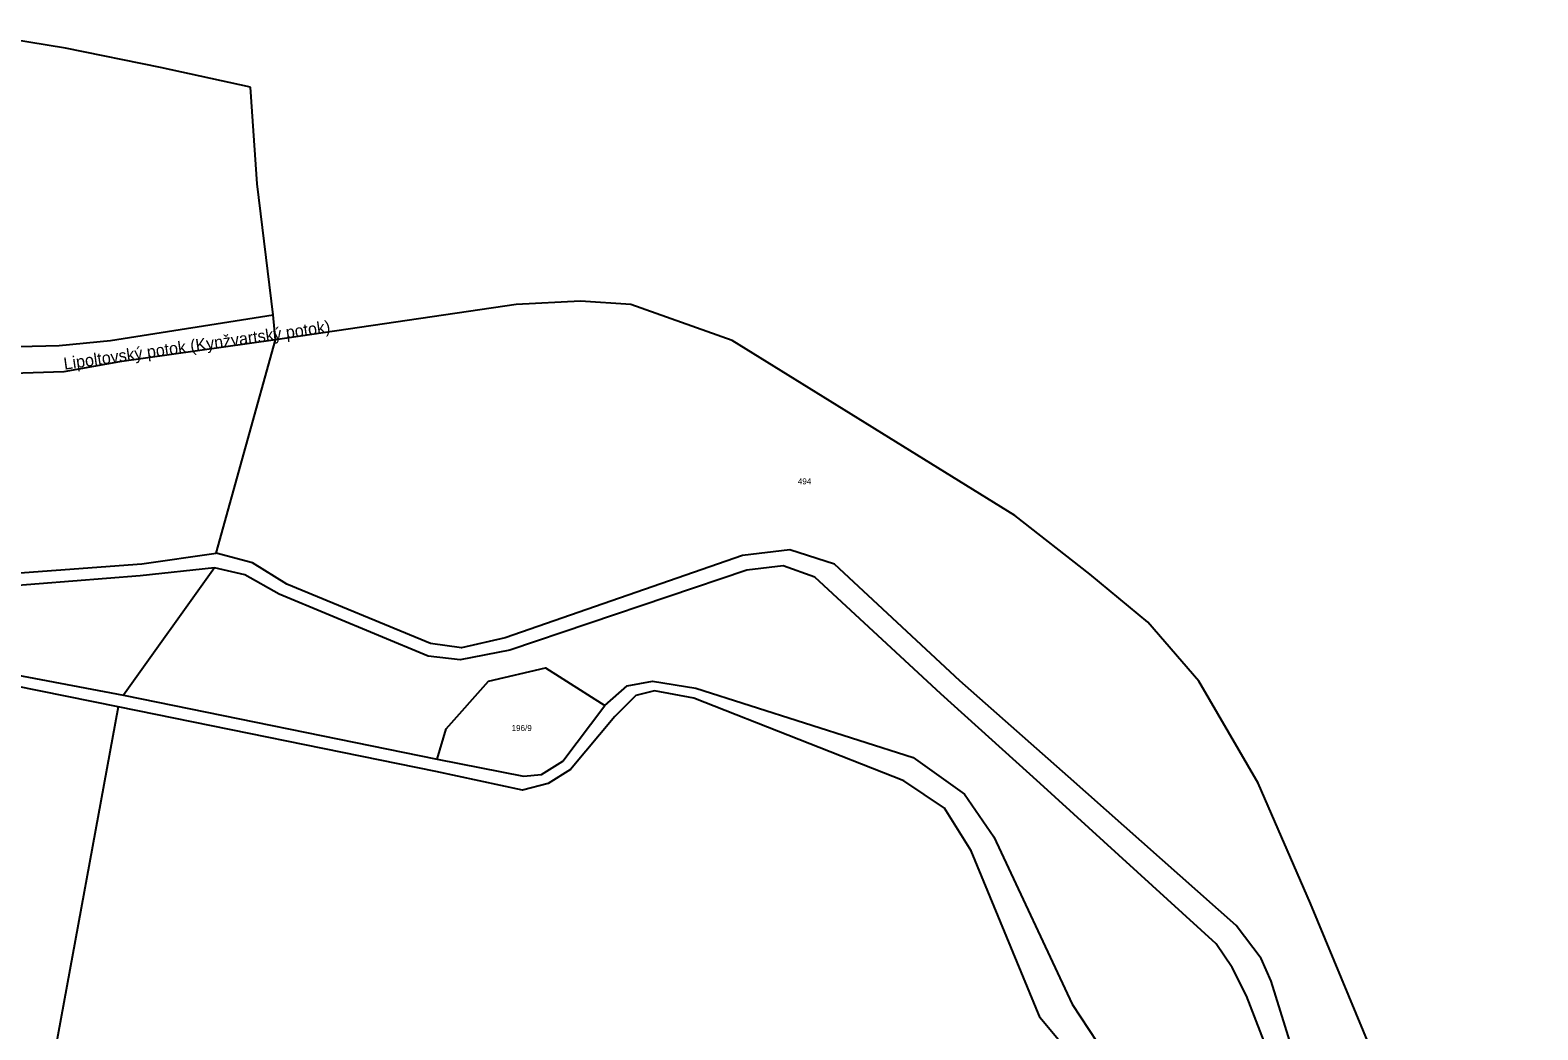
# Model space of a CAD drawing. Extents: x -880531 to -877616, y -1023932 to -1021350.
# Drawn here: x -878177.4 to -877751.2, y -1022635.5 to -1022353.1 of the extents above; entities that cross this region are included whole.
import ezdxf

# ---------------------------------------------------------------- set-up
doc = ezdxf.new("R2010")
doc.units = 0
for name, color, linetype in [('Hranice parcel', 7, 'Continuous'), ('Parcelní čísla', 7, 'Continuous'), ('Pop  PČ popisy', 7, 'Continuous')]:
    doc.layers.add(name, color=color, linetype=linetype)

msp = doc.modelspace()

# ---------------------------------------------------------------- linework, layer by layer
at = {"layer": 'Hranice parcel'}
for p, q in [((-878114.65, -1022376), (-878115.1, -1022369.21)), ((-878113.29, -1022396.52), (-878114.65, -1022376)), ((-878108.69, -1022433.47), (-878113.29, -1022396.52)), ((-878021.82, -1022429.61), (-878040.06, -1022430.56)), ((-878108.11, -1022440.58), (-878108.69, -1022433.47)), ((-878040.06, -1022430.56), (-878108.11, -1022440.58)), ((-878124.82, -1022500.78), (-878108.11, -1022440.58)), ((-878125.35, -1022504.99), (-878151.01, -1022540.9)), ((-878151.01, -1022540.9), (-878062.4, -1022559.06)), ((-878152.5, -1022544.22), (-878174.22, -1022662.33))]:
    msp.add_line(p, q, dxfattribs=at)
for points in [[(-878115.1, -1022369.21), (-878140.56, -1022363.64), (-878167.43, -1022358.13), (-878198.58, -1022353.06)], [(-877774.21, -1022699.12), (-877815.48, -1022599.78), (-877830.28, -1022565.82), (-877847.02, -1022536.96), (-877861.42, -1022520.32), (-877877.81, -1022506.75), (-877899.07, -1022490.23), (-877979.01, -1022440.72), (-878007.65, -1022430.59), (-878021.82, -1022429.61)], [(-878452.29, -1022470.77), (-878434.2, -1022474.39), (-878410.19, -1022472.17), (-878361.38, -1022456.95), (-878336.49, -1022449.29), (-878323.26, -1022446.51), (-878300.76, -1022445.25), (-878207.33, -1022443.11), (-878169.2, -1022442.13), (-878154.71, -1022440.73), (-878108.69, -1022433.47)], [(-878108.11, -1022440.58), (-878152.15, -1022446.77), (-878167.86, -1022449.63), (-878217.16, -1022451.24), (-878301.33, -1022453.9), (-878333.67, -1022456.67), (-878366.21, -1022467.52), (-878407.13, -1022480.7), (-878435.64, -1022482.95), (-878455.12, -1022478.73), (-878537.04, -1022450.63), (-878561.34, -1022444.97), (-878578.99, -1022444.28), (-878605.69, -1022449.33), (-878637.81, -1022454.4), (-878653.86, -1022459.64), (-878669.06, -1022467.56), (-878706.56, -1022499.73), (-878724.15, -1022512.39), (-878736.44, -1022518.55), (-878757.9, -1022522.41)], [(-878757.9, -1022522.41), (-878743.38, -1022532.72), (-878730.23, -1022539.4), (-878709.85, -1022535.98), (-878694.32, -1022525.35), (-878670.27, -1022495.13), (-878649.48, -1022475.44), (-878635.27, -1022470.68), (-878614.41, -1022478.04), (-878543.73, -1022482.35), (-878506.92, -1022500.7), (-878475.11, -1022508.02), (-878399.08, -1022508.59), (-878373.94, -1022502.74), (-878346.19, -1022490.2), (-878334.94, -1022490.41), (-878279.22, -1022499.74), (-878220.51, -1022507.42), (-878194.43, -1022507.39), (-878145.84, -1022503.8), (-878124.82, -1022500.78)], [(-878125.35, -1022504.99), (-878146.35, -1022507.21), (-878194.02, -1022510.96), (-878220.76, -1022511.05), (-878280.27, -1022503.97), (-878335.4, -1022493.58), (-878344.86, -1022493.55), (-878371.73, -1022505.4), (-878399.1, -1022512.43), (-878475.7, -1022511.16), (-878508.77, -1022503.35), (-878545.47, -1022484.68), (-878615.6, -1022481.24), (-878635.5, -1022474.3), (-878648.14, -1022478.45), (-878668.08, -1022496.96), (-878691.68, -1022527.88), (-878708.19, -1022539.68), (-878731.2, -1022543.61), (-878748.07, -1022535.1), (-878763.51, -1022523.14)], [(-877774.21, -1022699.12), (-877785.15, -1022681.23), (-877817.84, -1022649.87), (-877826.63, -1022621.76), (-877829.39, -1022615.33), (-877836.46, -1022606.02), (-877883.97, -1022563.9), (-877914.65, -1022536.94), (-877950.08, -1022503.93), (-877962.7, -1022499.85), (-877976.09, -1022501.47), (-878043.14, -1022524.77), (-878055.52, -1022527.59), (-878064.21, -1022526.36), (-878104.86, -1022509.57), (-878114.56, -1022503.51), (-878124.82, -1022500.78)], [(-877810.95, -1022891.71), (-877757.7, -1022868.07), (-877755.3, -1022863.36), (-877756.99, -1022844.34), (-877751.2, -1022776.89), (-877754.01, -1022763.91), (-877778.95, -1022701.2), (-877790.12, -1022684.76), (-877822.46, -1022654.59), (-877833.6, -1022625.94), (-877837.59, -1022617.9), (-877842.13, -1022611.17), (-877891.85, -1022565.86), (-877919.95, -1022540.56), (-877955.55, -1022507.61), (-877964.52, -1022504.4), (-877974.82, -1022505.6), (-878041.79, -1022528.2), (-878055.84, -1022531), (-878064.89, -1022529.96), (-878107.07, -1022512.45), (-878116.76, -1022506.91), (-878125.35, -1022504.99)], [(-878772.34, -1022525.45), (-878758.55, -1022537.32), (-878734.74, -1022552.47), (-878725.11, -1022552.52), (-878697.59, -1022542.6), (-878692.56, -1022542.42), (-878672.91, -1022533.58), (-878660.33, -1022531.18), (-878648.04, -1022531.76), (-878616.24, -1022536.33), (-878607.61, -1022539.29), (-878559.76, -1022547.29), (-878533.18, -1022551.67), (-878521.77, -1022552.65), (-878440.9, -1022540.29), (-878419.64, -1022538.34), (-878389.99, -1022539.7), (-878317.85, -1022548.39), (-878303.92, -1022544.55), (-878256.37, -1022525.75), (-878245.48, -1022524.13), (-878233.68, -1022525.33), (-878151.01, -1022540.9)], [(-878152.5, -1022544.22), (-878234.05, -1022527.78), (-878244.93, -1022527.2), (-878256.18, -1022528.49), (-878262.91, -1022531.2)], [(-878062.4, -1022559.06), (-878059.82, -1022550.43), (-878047.81, -1022536.98), (-878031.74, -1022533.19), (-878015.01, -1022543.9)], [(-878015.01, -1022543.9), (-878008.64, -1022538.33), (-878001.45, -1022536.99), (-877989.21, -1022538.94), (-877927.83, -1022558.6), (-877913.24, -1022568.89), (-877905, -1022581.01), (-877882.83, -1022628.25), (-877875.74, -1022639)], [(-877881.25, -1022644.92), (-877891.87, -1022632.09), (-877911.37, -1022584.94), (-877918.91, -1022572.84), (-877930.4, -1022565.15), (-877989.82, -1022541.75), (-878000.9, -1022539.74), (-878006.19, -1022541.03), (-878012.13, -1022546.99), (-878024.63, -1022561.95), (-878030.95, -1022565.94), (-878038.25, -1022567.79), (-878062.75, -1022562.53), (-878152.5, -1022544.22)], [(-878062.4, -1022559.06), (-878037.99, -1022563.86), (-878032.84, -1022563.38), (-878026.83, -1022559.57), (-878015.01, -1022543.9)]]:
    msp.add_lwpolyline(points, dxfattribs=at)

# ---------------------------------------------------------------- texts
at = {"layer": 'Parcelní čísla'}
for s, p in [('494', (-877960.39, -1022481.38)), ('196/9', (-878041.32, -1022551.08))]:
    msp.add_text(s, height=1.7, dxfattribs=at).set_placement(p)
at = {"layer": 'Pop  PČ popisy'}
msp.add_text('Lipoltovský potok (Kynžvartský potok)', height=3.4, rotation=8, dxfattribs=at).set_placement((-878167.723, -1022449.005))

doc.saveas('drawing.dxf')
